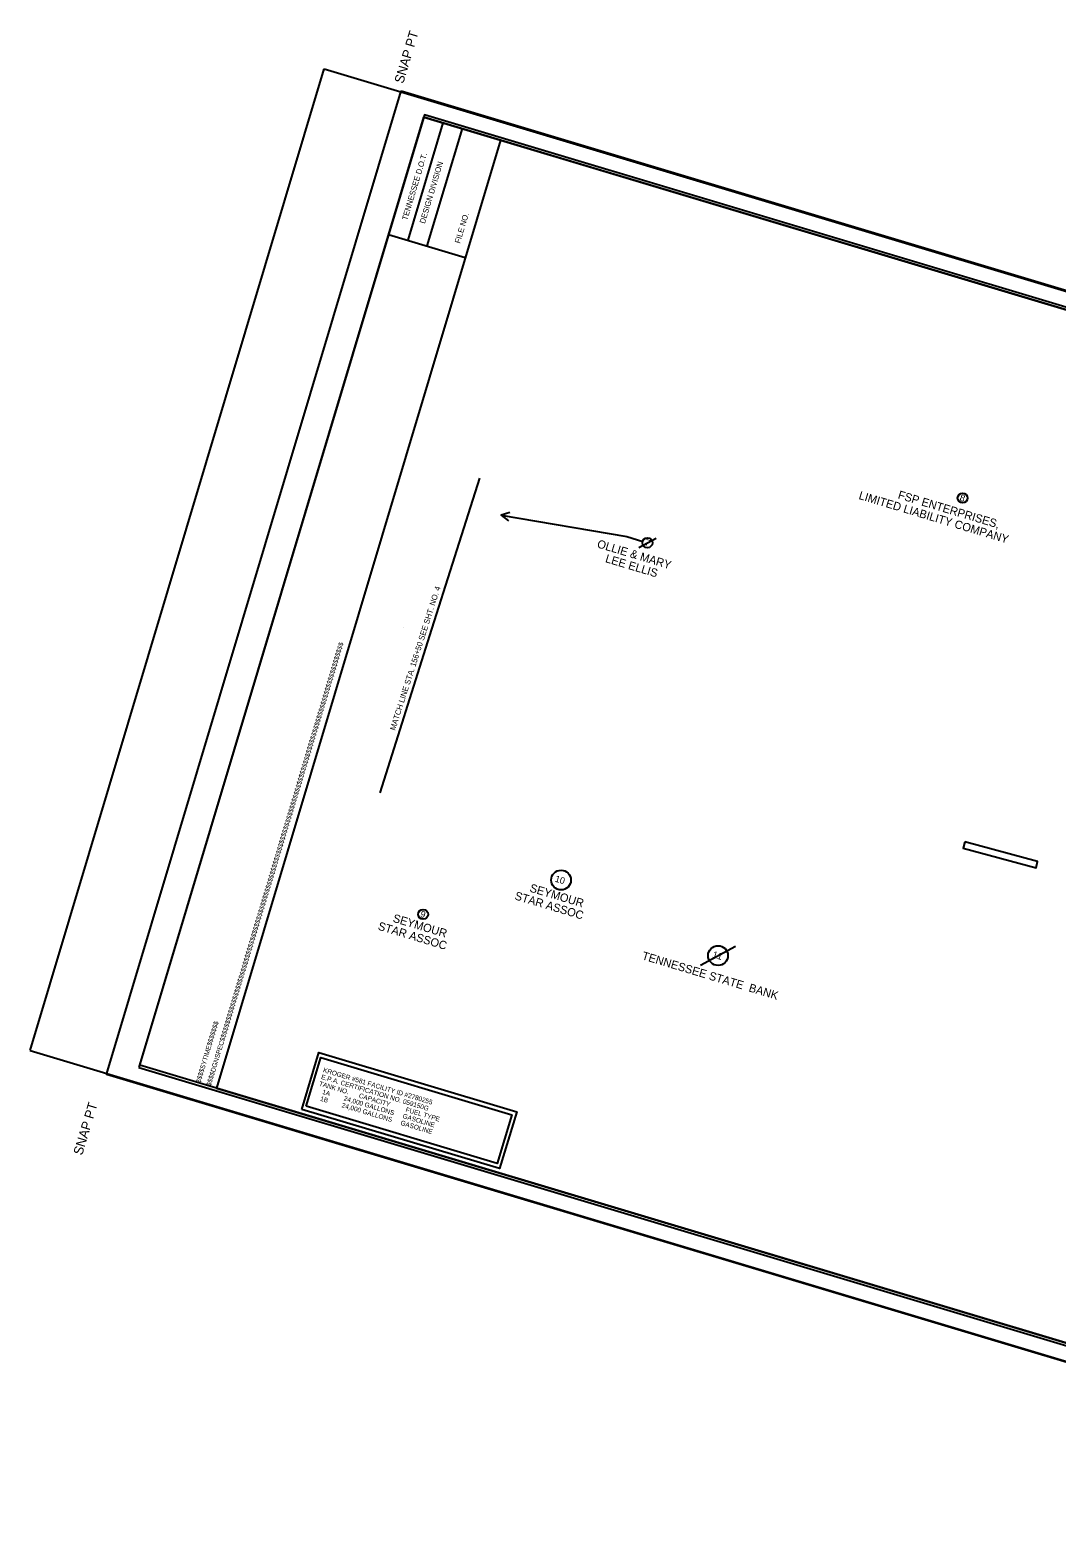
# Model space of a CAD drawing. Extents: x 2627582 to 2629622, y 568931 to 570612.
# Drawn here: x 2627582 to 2628672, y 569012 to 570612 of the extents above; entities that cross this region are included whole.
import ezdxf

# ---------------------------------------------------------------- set-up
doc = ezdxf.new("R2010")
doc.units = 0
for name, color, linetype in [('DESIGN - CENTERLINE - Proposed Text', 7, 'Continuous'), ('DESIGN - SCRATCH - User 1', 7, 'Continuous'), ('DESIGN - SHEET - Corner Text', 7, 'Continuous'), ('DESIGN - SHEET - Light Grid', 7, 'Continuous'), ('DESIGN - SHEET - Linework', 7, 'Continuous'), ('DESIGN - SHEET - Plot Shape', 7, 'Continuous'), ('DESIGN - UTILITIES - Gas with Text', 7, 'Continuous'), ('SURVEY - PROJECT INFORMATION and NOTES', 7, 'Continuous'), ('SURVEY - PROPERTY - Owners', 7, 'Continuous'), ('SURVEY - PROPERTY - Tract Numbers', 7, 'Continuous')]:
    doc.layers.add(name, color=color, linetype=linetype)

msp = doc.modelspace()

# ---------------------------------------------------------------- linework, layer by layer
at = {"layer": 'DESIGN - CENTERLINE - Proposed Text'}
msp.add_lwpolyline([(2627953.5, 569802.8), (2628006.4, 569969.6), (2628059.3, 570136.4)], dxfattribs=at)
at = {"layer": 'DESIGN - SCRATCH - User 1'}
msp.add_line((2627978.5, 569977.9), (2627978.5, 569977.9), dxfattribs=at)
at = {"layer": 'DESIGN - SHEET - Light Grid'}
msp.add_lwpolyline([(2627697.6, 569511.4), (2629292.5, 569033.3), (2629595.5, 570043.9), (2628000.6, 570522)], close=True, dxfattribs=at)
at = {"layer": 'DESIGN - SHEET - Linework'}
for p, q in [((2627582.1, 569529.2), (2627894.3, 570570.8)), ((2627894.3, 570570.8), (2629618.5, 570053.9)), ((2628020.2, 570513.5), (2627982.9, 570389.1)), ((2628040.6, 570507.4), (2628003.3, 570383)), ((2627582.1, 569529.2), (2629306.3, 569012.3))]:
    msp.add_line(p, q, dxfattribs=at)
for points in [[(2628081.3, 570495.2), (2627999.9, 570519.6), (2627962.6, 570395.2), (2628044, 570370.8)], [(2628081.3, 570495.2), (2627779.8, 569489.4), (2629287.7, 569037.4), (2629589.2, 570043.2), (2628081.3, 570495.2)]]:
    msp.add_lwpolyline(points, dxfattribs=at)
at = {"layer": 'DESIGN - SHEET - Plot Shape'}
for points in [[(2627975.9, 570547.4), (2629604.3, 570059.2), (2629291.5, 569015.7), (2627663.1, 569503.8)], [(2627999.9, 570519.6), (2629589.2, 570043.2), (2629287.7, 569037.4), (2627698.4, 569513.8)]]:
    msp.add_lwpolyline(points, close=True, dxfattribs=at)
at = {"layer": 'DESIGN - UTILITIES - Gas with Text'}
msp.add_lwpolyline([(2628574.2, 569750.6), (2628572.4, 569744.1), (2628649.7, 569723.3), (2628651.4, 569729.8)], close=True, dxfattribs=at)
at = {"layer": 'SURVEY - PROJECT INFORMATION and NOTES'}
for points in [[(2627870.5, 569466.9), (2627888.6, 569527.3), (2628098.5, 569464.3), (2628080.4, 569404)], [(2627875.2, 569470.2), (2627890.7, 569521.9), (2628093.3, 569461.2), (2628077.8, 569409.5)]]:
    msp.add_lwpolyline(points, close=True, dxfattribs=at)
at = {"layer": 'SURVEY - PROPERTY - Tract Numbers'}
for p, q in [((2628228.1, 570063), (2628246.6, 570073)), ((2628293.7, 569620), (2628330.7, 569640))]:
    msp.add_line(p, q, dxfattribs=at)
for points in [[(2628091.4, 570100), (2628082, 570097.2), (2628089.9, 570091.4)], [(2628082, 570097.2), (2628215.5, 570074.5)], [(2628215.5, 570074.5), (2628232.3, 570069.5)]]:
    msp.add_lwpolyline(points, dxfattribs=at)
for centre, radius in [((2628571.8, 570115.5), 5.25), ((2628237.3, 570068), 5.25), ((2628145.6, 569710.2), 10.5), ((2627999.2, 569673.8), 5.25), ((2628312.2, 569630), 10.5)]:
    msp.add_circle(centre, radius, dxfattribs=at)

# ---------------------------------------------------------------- texts
at = {"layer": 'DESIGN - CENTERLINE - Proposed Text'}
msp.add_text('MATCH LINE STA. 156+50 SEE SHT. NO. 4', height=6, rotation=72.3958, dxfattribs=at).set_placement((2627969.5, 569868.4))
at = {"layer": 'DESIGN - SHEET - Corner Text'}
for s, height, p in [('  SNAP PT', 10, (2627975.9, 570547.4)), ('TENNESSEE D.O.T.', 6, (2627982.3, 570409.6)), ('DESIGN DIVISION', 6, (2628001, 570406.1)), ('FILE NO.', 6, (2628038.3, 570385.1)), ('$$$$DGNSPEC$$$$$$$$$$$$$$$$$$$$$$$$$$$$$$$$$$$$$$$$$$$$$$$$$$$$$$$$$$$$$$$$$$$$$$$$$$$$$$$$$$$$$$$$$$$$$$$$$$$$$$$$$$$$$$$$$$$', 5.0001, (2627773.8, 569491.2)), ('$$$$SYTIME$$$$$$$', 5, (2627762.7, 569494.5)), ('SNAP PT  ', 10, (2627637.3, 569417.6))]:
    msp.add_text(s, height=height, rotation=73.3133, dxfattribs=at).set_placement(p)
at = {"layer": 'SURVEY - PROJECT INFORMATION and NOTES'}
for s, p in [('KROGER #581 FACILITY ID #2780255', (2627892.6, 569506.5)), ('TANK NO.      CAPACITY         FUEL TYPE', (2627888.3, 569492.1)), ('E.P.A. CERTIFICATION NO. 059150G', (2627890.5, 569499.3)), ('   1B        24,000 GALLONS     GASOLINE', (2627884, 569477.8)), ('   1A        24,000 GALLONS     GASOLINE', (2627886.2, 569485))]:
    msp.add_text(s, height=5, rotation=343.3133, dxfattribs=at).set_placement(p)
at = {"layer": 'SURVEY - PROPERTY - Owners'}
for s, p in [('LIMITED LIABILITY COMPANY', (2628460.9, 570114.6)), ('FSP ENTERPRISES,', (2628502.5, 570115.2)), ('OLLIE & MARY', (2628183.2, 570063.2)), ('LEE ELLIS', (2628191.9, 570047.6)), ('STAR ASSOC', (2628095.7, 569689.8)), ('SEYMOUR', (2628111.6, 569698.1)), ('STAR ASSOC', (2627950.6, 569657.7)), ('SEYMOUR', (2627966.4, 569666)), ('TENNESSEE STATE  BANK', (2628230.8, 569626.2))]:
    msp.add_text(s, height=8.75, rotation=343.3133, dxfattribs=at).set_placement(p)
at = {"layer": 'SURVEY - PROPERTY - Tract Numbers'}
for s, p in [('8', (2628568.2, 570112.9)), ('7', (2628233.8, 570065.4)), ('10', (2628138.5, 569708.6)), ('9', (2627995.6, 569671.2)), ('11', (2628305.7, 569628.3))]:
    msp.add_text(s, height=7, rotation=343.3133, dxfattribs=at).set_placement(p)

doc.saveas('drawing.dxf')
